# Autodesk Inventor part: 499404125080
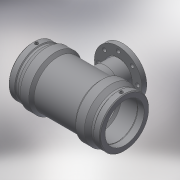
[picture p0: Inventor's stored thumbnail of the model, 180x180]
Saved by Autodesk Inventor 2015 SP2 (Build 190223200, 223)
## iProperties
Created: 2017-06
Part Number: 499404125080
Material: Generic
Description: PLASSON FLANGED TEE 125x80x125
Document SubType Name: Modeling
Designer: KIM
Mass: 57.3761 g
Surface Area: 241.06 cm^2
Volume: 57.3761 cm^3
Density: 1 g/cm^3
Appearance: Default
Author: KIM
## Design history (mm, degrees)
derived "499404.ipt"
feature "Solid1::499404.ipt"
tag "TaggingFeature1"
body "Solid1"
other parameters: "d13" = 382, "d14" = 17.6296, "d17" = 112.5, "d18" = 125, "d19" = 3.52592, "d20" = 168 deg, "d22" = 153.45, "d23" = 165, "d24" = 148.8465, "d25" = 135 deg, "d26" = 267.4, "d27" = 135 deg, "d29" = 88, "d35" = 15, "d39" = 5 deg, "d45" = 4, "d46" = 14, "d47" = 0, "d55" = 148.5, "d56" = 165, "d57" = 133.7, "d58" = 135 deg, "d59" = 86, "d60" = 86, "d61" = 135 deg, "d72" = 173.81, "d73" = 86.905, "d87" = 138, "d89" = 96, "d91" = 15 deg, "d92" = 104, "d95" = 4.14, "d97" = 18, "d100" = 0, "d102" = 360 deg, "d105" = 0, "d107" = 0, "d108" = 3, "d109" = 0, "d110" = 25.8, "d111" = 8.6, "d_" = 125, "L_" = 382, "L_1" = 86, "D_" = 165, "A_" = 88, "d_2" = 12, "d_1" = 138, "s_" = 18
